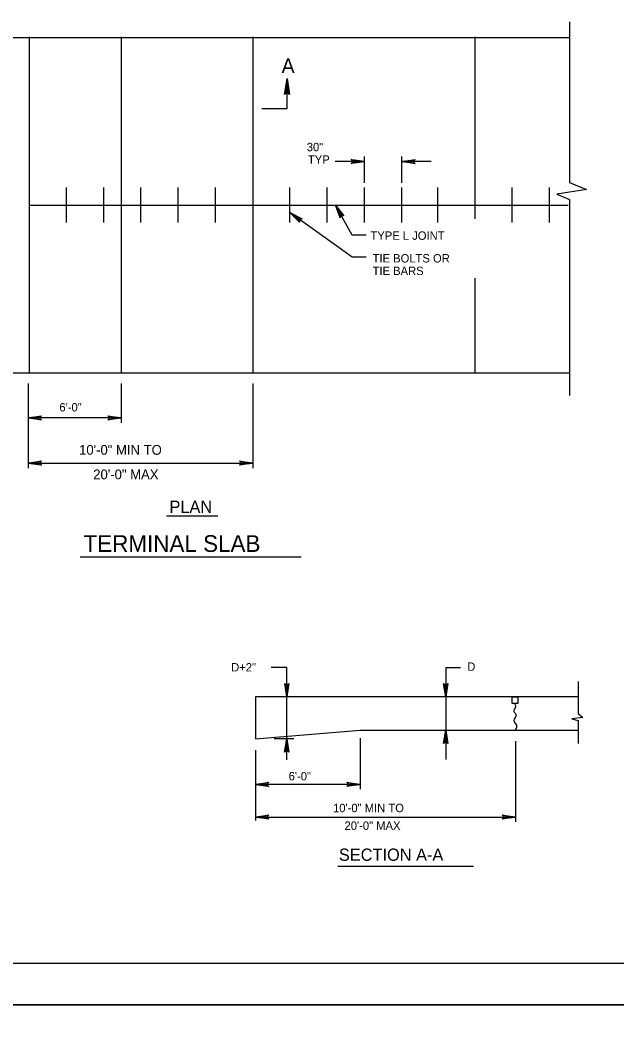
# Model space of a CAD drawing. Extents: x 637877 to 639321, y 297902 to 299090.
# Drawn here: x 638794.1 to 639007.7, y 298488.1 to 298847.9 of the extents above; entities that cross this region are included whole.
import ezdxf

# ---------------------------------------------------------------- set-up
doc = ezdxf.new("R2010")
doc.units = 0
for name, color, linetype in [('1', 7, 'Continuous'), ('2', 7, 'Continuous'), ('3', 7, 'Continuous'), ('PLT-BNDY', 7, 'Continuous')]:
    doc.layers.add(name, color=color, linetype=linetype)

msp = doc.modelspace()

# ---------------------------------------------------------------- linework, layer by layer
at = {"layer": '1'}
msp.add_lwpolyline([(639241.51, 298510.57), (639241.51, 299074.57), (638455.51, 299074.57), (638455.51, 298510.57), (639241.51, 298510.57), (639241.51, 298536.93), (639041.51, 298536.93), (639041.51, 298601.61), (639241.51, 298601.61), (639241.51, 298630.57), (639041.51, 298630.57), (639041.51, 298510.57), (639120.32, 298510.57), (639120.32, 298536.93), (639120.32, 298510.57), (639197.32, 298510.57), (639197.32, 298536.93), (639197.32, 298524.61), (639241.51, 298524.61)], dxfattribs=at)
msp.add_lwpolyline([(638970.13, 298605.82), (638972.22, 298605.82), (638972.22, 298603.38), (638970.13, 298603.38)], close=True, dxfattribs=at)
msp.add_spline([(638971.41, 298593.94), (638971.82, 298595.67), (638970.91, 298597.32), (638971.66, 298599.48), (638970.83, 298600.47), (638971.49, 298602.29), (638971.16, 298603.36)], degree=3, dxfattribs=at)
at = {"layer": '2'}
for p, q in [((638990.64, 298847.29), (638990.64, 298789.8)), ((638715.64, 298841.76), (638990.64, 298841.76)), ((638795.72, 298841.76), (638870.76, 298841.76)), ((638797.3, 298841.98), (638797.3, 298721.76)), ((638830.19, 298841.98), (638830.19, 298721.76)), ((638877.3, 298841.98), (638877.3, 298721.76)), ((638956.84, 298841.98), (638956.84, 298776.89)), ((638917.3, 298789.76), (638917.3, 298799.09)), ((638930.64, 298789.76), (638930.64, 298799.09)), ((638917.3, 298797.34), (638906.8, 298797.34)), ((638941.14, 298797.34), (638930.64, 298797.34)), ((638797.3, 298781.76), (638990.18, 298781.76)), ((638810.64, 298781.76), (638810.64, 298781.76)), ((638817.3, 298781.76), (638817.3, 298781.76)), ((638823.97, 298781.76), (638823.97, 298781.76)), ((638830.64, 298781.76), (638830.64, 298781.76)), ((638837.3, 298781.76), (638837.3, 298781.76)), ((638843.97, 298781.76), (638843.97, 298781.76)), ((638850.64, 298781.76), (638850.64, 298781.76)), ((638857.3, 298781.76), (638857.3, 298781.76)), ((638863.97, 298781.76), (638863.97, 298781.76)), ((638870.64, 298781.76), (638870.64, 298781.76)), ((638877.3, 298781.76), (638877.3, 298781.76)), ((638883.97, 298781.76), (638883.97, 298781.76)), ((638883.97, 298781.76), (638883.97, 298781.76)), ((638883.97, 298781.76), (638883.97, 298781.76)), ((638890.64, 298781.76), (638890.64, 298781.76)), ((638897.3, 298781.76), (638897.3, 298781.76)), ((638903.97, 298781.76), (638903.97, 298781.76)), ((638910.64, 298781.76), (638910.64, 298781.76)), ((638917.3, 298781.76), (638917.3, 298781.76)), ((638923.97, 298781.76), (638923.97, 298781.76)), ((638930.64, 298781.76), (638930.64, 298781.76)), ((638936.84, 298781.76), (638936.84, 298781.76)), ((638937.3, 298781.76), (638937.3, 298781.76)), ((638943.51, 298781.76), (638943.51, 298781.76)), ((638943.97, 298781.76), (638943.97, 298781.76)), ((638950.18, 298781.76), (638950.18, 298781.76)), ((638950.64, 298781.76), (638950.64, 298781.76)), ((638956.84, 298781.76), (638956.84, 298781.76)), ((638957.3, 298781.76), (638957.3, 298781.76)), ((638963.51, 298781.76), (638963.51, 298781.76)), ((638963.97, 298781.76), (638963.97, 298781.76)), ((638963.97, 298781.76), (638963.97, 298781.76)), ((638963.97, 298781.76), (638963.97, 298781.76)), ((638963.97, 298781.76), (638963.97, 298781.76)), ((638963.97, 298781.76), (638963.97, 298781.76)), ((638970.18, 298781.76), (638970.18, 298781.76)), ((638970.64, 298781.76), (638970.64, 298781.76)), ((638976.84, 298781.76), (638976.84, 298781.76)), ((638977.3, 298781.76), (638977.3, 298781.76)), ((638983.51, 298781.76), (638983.51, 298781.76)), ((638983.97, 298781.76), (638983.97, 298781.76)), ((638990.64, 298783.77), (638990.64, 298713.6)), ((638956.84, 298755.57), (638956.84, 298721.76)), ((638715.64, 298721.76), (638990.64, 298721.76)), ((638796.97, 298717.89), (638796.97, 298703.83)), ((638796.97, 298717.89), (638796.97, 298687.68)), ((638830.19, 298717.89), (638830.19, 298703.83)), ((638877.3, 298717.89), (638877.3, 298687.68)), ((638830.19, 298705.58), (638796.97, 298705.58)), ((638796.97, 298689.43), (638877.3, 298689.43)), ((638889.5, 298616.31), (638883.89, 298616.31)), ((638889.5, 298590.81), (638889.5, 298616.31)), ((638946.37, 298616.31), (638946.37, 298605.81)), ((638993.8, 298611.34), (638993.8, 298599.86)), ((638971.28, 298605.81), (638878.28, 298605.81)), ((638878.28, 298605.81), (638878.28, 298590.81)), ((638993.8, 298605.81), (638971.28, 298605.81)), ((638878.28, 298590.81), (638915.78, 298593.93)), ((638915.78, 298593.93), (638993.8, 298593.93)), ((638993.8, 298597.32), (638993.8, 298589.11)), ((638892.05, 298590.81), (638884.93, 298590.81)), ((638889.5, 298583.28), (638889.5, 298590.81)), ((638915.78, 298591.03), (638915.78, 298572.72)), ((638878.28, 298586.73), (638878.28, 298561.52)), ((638971.41, 298589.91), (638971.41, 298561.04)), ((638915.78, 298574.47), (638878.28, 298574.47)), ((638878.28, 298562.79), (638971.41, 298562.79))]:
    msp.add_line(p, q, dxfattribs=at)
for points in [[(638880.6, 298816.29), (638889.6, 298816.29), (638889.6, 298827.09)], [(638888.91, 298821.64), (638889.31, 298821.85), (638889.6, 298827.09), (638888.91, 298821.64), (638888.68, 298821.36), (638889.6, 298827.09), (638889.86, 298821.85), (638890.25, 298821.66), (638889.6, 298827.09), (638890.51, 298821.36), (638890.25, 298821.66)], [(638912.76, 298797.91), (638912.93, 298797.58), (638917.3, 298797.34), (638912.76, 298797.91), (638912.53, 298798.11), (638917.3, 298797.34), (638912.93, 298797.13), (638912.78, 298796.8), (638917.3, 298797.34), (638912.53, 298796.58), (638912.78, 298796.8)], [(638935.18, 298796.77), (638935.01, 298797.1), (638930.64, 298797.34), (638935.18, 298796.77), (638935.41, 298796.57), (638930.64, 298797.34), (638935.01, 298797.56), (638935.16, 298797.88), (638930.64, 298797.34), (638935.41, 298798.1), (638935.16, 298797.88)], [(638990.64, 298789.8), (638996.76, 298787.35), (638986.2, 298785.64), (638990.64, 298783.77)], [(638810.64, 298775.51), (638810.64, 298781.76), (638810.64, 298788.01)], [(638823.97, 298775.51), (638823.97, 298781.76), (638823.97, 298788.01)], [(638837.3, 298775.51), (638837.3, 298781.76), (638837.3, 298788.01)], [(638850.64, 298775.51), (638850.64, 298781.76), (638850.64, 298788.01)], [(638863.97, 298775.51), (638863.97, 298781.76), (638863.97, 298788.01)], [(638890.64, 298775.51), (638890.64, 298781.76), (638890.64, 298788.01)], [(638903.97, 298775.51), (638903.97, 298781.76), (638903.97, 298788.01)], [(638917.3, 298775.51), (638917.3, 298781.76), (638917.3, 298788.01)], [(638930.64, 298775.51), (638930.64, 298781.76), (638930.64, 298788.01)], [(638943.51, 298775.51), (638943.51, 298781.76), (638943.51, 298788.01)], [(638970.18, 298775.51), (638970.18, 298781.76), (638970.18, 298788.01)], [(638983.51, 298775.51), (638983.51, 298781.76), (638983.51, 298788.01)], [(638917.93, 298770.96), (638912.93, 298770.96), (638906.88, 298781.76)], [(638908.61, 298777.52), (638908.81, 298777.83), (638906.88, 298781.76), (638908.61, 298777.52), (638908.55, 298777.22), (638906.88, 298781.76), (638909.21, 298778.06), (638909.57, 298778.08), (638906.88, 298781.76), (638909.88, 298777.97), (638909.57, 298778.08)], [(638917.93, 298763.15), (638912.93, 298763.15), (638890.64, 298779.05)], [(638894, 298775.95), (638894.06, 298776.31), (638890.64, 298779.05), (638894, 298775.95), (638894.08, 298775.65), (638890.64, 298779.05), (638894.32, 298776.69), (638894.64, 298776.86), (638890.64, 298779.05), (638894.96, 298776.89), (638894.64, 298776.86)], [(638801.51, 298705.01), (638801.34, 298705.34), (638796.97, 298705.58), (638801.51, 298705.01), (638801.75, 298704.81), (638796.97, 298705.58), (638801.34, 298705.79), (638801.5, 298706.12), (638796.97, 298705.58), (638801.75, 298706.34), (638801.5, 298706.12)], [(638825.65, 298706.15), (638825.82, 298705.82), (638830.19, 298705.58), (638825.65, 298706.15), (638825.42, 298706.35), (638830.19, 298705.58), (638825.82, 298705.36), (638825.66, 298705.04), (638830.19, 298705.58), (638825.42, 298704.82), (638825.66, 298705.04)], [(638801.51, 298688.86), (638801.34, 298689.19), (638796.97, 298689.43), (638801.51, 298688.86), (638801.75, 298688.66), (638796.97, 298689.43), (638801.34, 298689.65), (638801.5, 298689.97), (638796.97, 298689.43), (638801.75, 298690.19), (638801.5, 298689.97)], [(638872.76, 298690), (638872.93, 298689.67), (638877.3, 298689.43), (638872.76, 298690), (638872.53, 298690.2), (638877.3, 298689.43), (638872.93, 298689.21), (638872.78, 298688.89), (638877.3, 298689.43), (638872.53, 298688.67), (638872.78, 298688.89)], [(638946.37, 298616.31), (638951.62, 298616.31)], [(638890.07, 298610.35), (638889.75, 298610.18), (638889.5, 298605.81), (638890.07, 298610.35), (638890.27, 298610.58), (638889.5, 298605.81), (638889.29, 298610.18), (638888.96, 298610.34), (638889.5, 298605.81), (638888.75, 298610.58), (638888.96, 298610.34)], [(638946.94, 298610.35), (638946.61, 298610.18), (638946.37, 298605.81), (638946.94, 298610.35), (638947.14, 298610.58), (638946.37, 298605.81), (638946.15, 298610.18), (638945.83, 298610.34), (638946.37, 298605.81), (638945.61, 298610.58), (638945.83, 298610.34)], [(638946.37, 298605.81), (638946.37, 298583.43)], [(638993.8, 298599.86), (638995.48, 298598.42), (638991.58, 298597.99), (638993.8, 298597.32)], [(638945.8, 298589.39), (638946.13, 298589.56), (638946.37, 298593.93), (638945.8, 298589.39), (638945.6, 298589.16), (638946.37, 298593.93), (638946.58, 298589.57), (638946.91, 298589.4), (638946.37, 298593.93), (638947.13, 298589.16), (638946.91, 298589.4)], [(638888.94, 298586.27), (638889.26, 298586.44), (638889.5, 298590.81), (638888.94, 298586.27), (638888.74, 298586.03), (638889.5, 298590.81), (638889.72, 298586.44), (638890.05, 298586.28), (638889.5, 298590.81), (638890.26, 298586.03), (638890.05, 298586.28)], [(638882.82, 298573.9), (638882.65, 298574.23), (638878.28, 298574.47), (638882.82, 298573.9), (638883.05, 298573.7), (638878.28, 298574.47), (638882.65, 298574.69), (638882.81, 298575.01), (638878.28, 298574.47), (638883.05, 298575.23), (638882.81, 298575.01)], [(638911.24, 298575.04), (638911.41, 298574.71), (638915.78, 298574.47), (638911.24, 298575.04), (638911.01, 298575.24), (638915.78, 298574.47), (638911.41, 298574.26), (638911.25, 298573.93), (638915.78, 298574.47), (638911.01, 298573.71), (638911.25, 298573.93)], [(638882.82, 298562.22), (638882.65, 298562.55), (638878.28, 298562.79), (638882.82, 298562.22), (638883.05, 298562.02), (638878.28, 298562.79), (638882.65, 298563), (638882.81, 298563.33), (638878.28, 298562.79), (638883.05, 298563.55), (638882.81, 298563.33)], [(638966.87, 298563.36), (638967.04, 298563.03), (638971.41, 298562.79), (638966.87, 298563.36), (638966.64, 298563.56), (638971.41, 298562.79), (638967.04, 298562.57), (638966.88, 298562.25), (638971.41, 298562.79), (638966.64, 298562.03), (638966.88, 298562.25)]]:
    msp.add_lwpolyline(points, dxfattribs=at)
at = {"layer": '3'}
for p, q in [((638846.4, 298670.51), (638864.86, 298670.51)), ((638815.59, 298655.91), (638894.66, 298655.91)), ((638907.81, 298545.26), (638956.38, 298545.26))]:
    msp.add_line(p, q, dxfattribs=at)
at = {"layer": 'PLT-BNDY'}
for points in [[(638415.51, 299089.57), (639256.51, 299089.57), (639256.51, 298495.57), (638415.51, 298495.57)], [(638415.51, 298495.57), (639256.51, 298495.57), (639256.51, 297901.57), (638415.51, 297901.57)]]:
    msp.add_lwpolyline(points, close=True, dxfattribs=at)

# ---------------------------------------------------------------- texts
at = {"layer": '2'}
for s, p in [('30"', (638896.66, 298801.03)), ('TYP', (638897.07, 298796.53))]:
    msp.add_text(s, height=3, dxfattribs=at).set_placement(p)
at = {"layer": '3'}
for s, height, p in [('A', 5.25, (638887.64, 298828.97)), ('TYPE L JOINT', 2.9995, (638919.45, 298769.33)), ('TIE BOLTS OR', 2.9995, (638920.21, 298761.22)), ('TIE BARS', 2.999, (638920.21, 298756.72)), ('6\'-0"', 3, (638808.11, 298707.92)), ('10\'-0" MIN TO', 3.5, (638815.16, 298692.42)), ('20\'-0" MAX', 3.5, (638820.22, 298683.65)), ('PLAN', 4.375, (638847.51, 298671.62)), ('TERMINAL SLAB', 6, (638816.75, 298657.65)), ('D+2"', 3, (638869.59, 298614.88)), ('D', 3, (638954.11, 298615.11)), ('6\'-0"', 3, (638890.17, 298575.92)), ('10\'-0" MIN TO', 2.9998, (638906.06, 298564.54)), ('20\'-0" MAX', 3, (638910.17, 298558.21)), ('SECTION A-A', 4.375, (638908.15, 298547.14))]:
    msp.add_text(s, height=height, dxfattribs=at).set_placement(p)

doc.saveas('drawing.dxf')
